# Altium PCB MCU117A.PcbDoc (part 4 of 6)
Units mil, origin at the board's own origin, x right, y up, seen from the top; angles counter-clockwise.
Board outline 2300 x 6749.64 mil, 6 copper layers (Top Signal, GND, Middle Signal, PWR, GND2, Bottom Signal), stack 61.64 mil thick; 424 components, 343 nets, 1563 pads, 921 vias.
Unrouted connection lines stored in the file: 4.
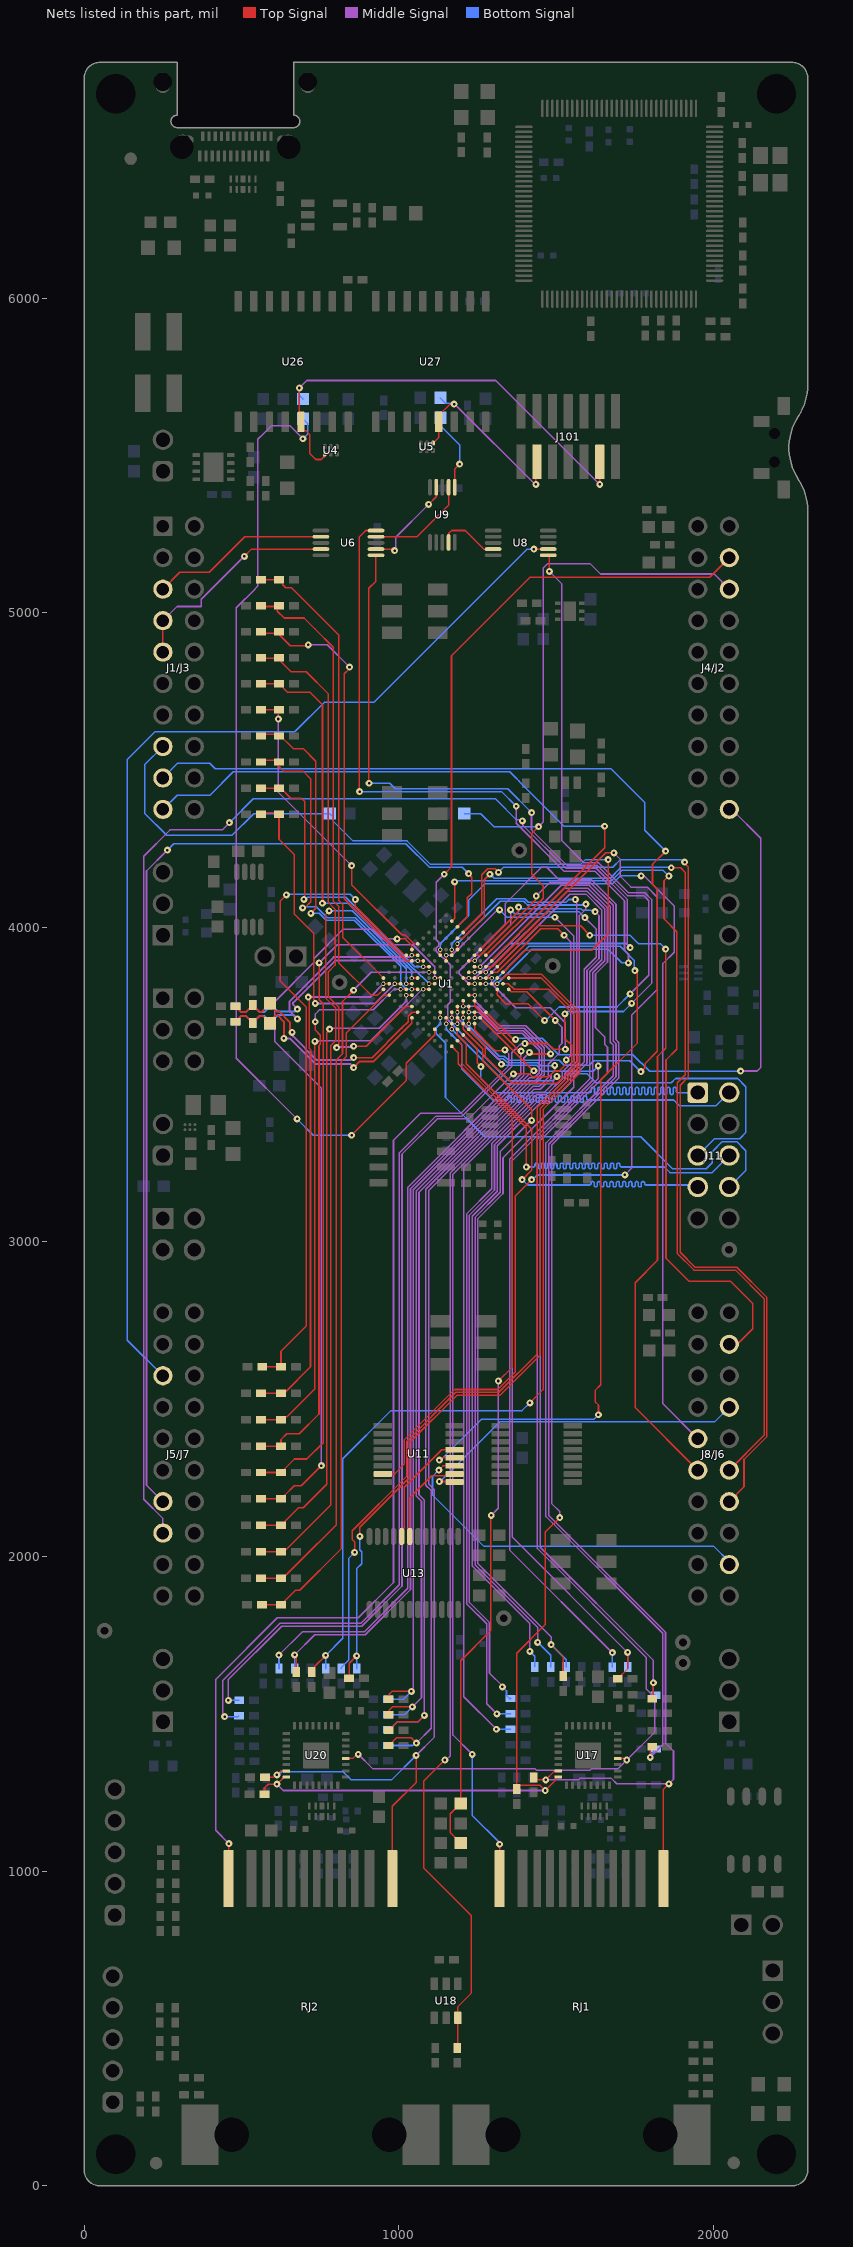
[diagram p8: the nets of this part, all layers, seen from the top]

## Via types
v1: diameter 22, hole 8, Top Signal to Bottom Signal, tented both sides, 821 vias
v2: diameter 14, hole 8, Top Signal to Bottom Signal, tented both sides, 82 vias
v3: diameter 19.68, hole 7.87, Top Signal to Bottom Signal, tented top, 14 vias
v4: diameter 15.75, hole 7.87, Top Signal to Bottom Signal, tented both sides, 2 vias
v5: diameter 19.68, hole 7.87, Top Signal to Bottom Signal, 2 vias

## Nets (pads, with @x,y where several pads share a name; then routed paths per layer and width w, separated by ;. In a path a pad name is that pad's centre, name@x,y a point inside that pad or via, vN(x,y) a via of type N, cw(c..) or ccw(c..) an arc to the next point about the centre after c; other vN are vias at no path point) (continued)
GPIO42: U1.C12 U6.6 | length 2639
  Top Signal w4: U1.C12@1312.81,3802.59 1312.81,3785.05 1340.29,3757.57 1409.23,3757.57
  Top Signal w5: v1(905.56,4457.76) 904.36,4458.97 904.36,5077.28 926.45,5099.38 926.45,5181.41 U6.6@927.34,5182.29 ; 1409.23,3757.57 v1(1462.86,3703.94)
  Middle Signal w5: v1(1421.5,4364.56) 1421.5,4309.46 1534.58,4196.38 1630.75,4196.38 1726.24,4100.89 1777.83,4100.89 1794.1,4084.62 1794.1,3847.43 v1(1735.08,3788.42)
  Bottom Signal w5: v1(905.56,4457.76) 970.51,4457.76 988.05,4440.23 1345.83,4440.23 v1(1421.5,4364.56) ; v1(1462.86,3703.94) 1466.46,3703.94 1509.2,3746.69 1693.35,3746.69 v1(1735.08,3788.42)
GPIO42_BP: J1/J3.4 J1/J3.5 U6.4 | length 709.9
  Top Signal w5: J1/J3.5@249.99,4874.64 J1/J3.4@249.99,4974.64 ; v1(509,5179.11) 531.86,5201.98 U6.4@752.14,5201.98
  Middle Signal w5: J1/J3.4@249.99,4974.64 294.99,5019.64 371.95,5019.64 371.95,5042.84 508.22,5179.11 v1(509,5179.11)
GPIO42_SCITX: U6.7 U9.9 | length 317.3
  Top Signal w5: U6.7@927.34,5201.98 981.13,5201.98 v1(986.18,5196.93) ; v1(1094.26,5344) 1118.5,5368.23 U9.9@1118.5,5398.49
  Middle Signal w5: v1(986.18,5196.93) 989.91,5200.67 989.91,5239.65 v1(1094.26,5344)
GPIO43: U1.C11 U6.10 | length 2589.7
  Top Signal w5: v1(875.05,4431.23) 874.62,4431.66 874.62,5241.35 894.31,5261.03 U6.10@927.34,5261.03 ; U1.C11@1294.71,3820.69 v2(1312.81,3820.69)
  Middle Signal w5: v1(1372.87,4384.62) 1372.87,4330.4 1524.89,4178.38 1623.29,4178.38 1717.06,4084.62 1717.06,3928.1 1729.67,3915.48 v1(1729.67,3887.06)
  Bottom Signal w4: v2(1312.81,3820.69) 1407.37,3915.25
  Bottom Signal w5: v1(875.05,4431.23) 1326.26,4431.23 v1(1372.87,4384.62) ; 1407.37,3915.25 1422.56,3930.44 1664.86,3930.44 1708.24,3887.06 v1(1729.67,3887.06)
GPIO43_BP: J1/J3.3 U6.2 | length 571.2
  Top Signal w5: J1/J3.3@249.99,5074.64 303.73,5128.38 397.49,5128.38 510.46,5241.35 U6.2@752.14,5241.35
GPIO43_SCIRX: U6.9 U9.7 | length 328.9
  Top Signal w5: U6.9@927.34,5241.35 1057.47,5241.35 1157.87,5341.74 U9.7@1157.87,5398.49
GPIO44: R146.2 R155.1 U1.F10 | length 2841.3
  Top Signal w5: v1(668.56,1687.49) 673.15,1682.89 R146.2@673.15,1632.93 ; U1.F10@1222.33,3784.5 v2(1240.43,3784.5) ; v1(1414.96,3602.28) 1419.56,3602.28 1424.45,3597.4 v1(1482.24,3597.4)
  Middle Signal w4: v2(1240.43,3784.5) 1240.43,3766.4 1319.69,3687.14 1402.56,3687.14 1479.25,3610.45 1479.25,3600.39 v1(1482.24,3597.4)
  Middle Signal w5: v1(668.56,1687.49) 732.72,1751.65 893.28,1751.65 1036.85,1895.21 1036.85,3169.28 1396.63,3529.06 1396.63,3583.95 v1(1414.96,3602.28)
  Bottom Signal w5: R155.1@668.56,1643.85 v1(668.56,1687.49)
GPIO45: R91.2 U1.F11 | length 2621.1
  Top Signal w4: U1.F11@1240.43,3766.4 1240.43,3748.77 1355.07,3634.12 1382.81,3606.38 v1(1388.33,3606.38)
  Middle Signal w5: v1(618.85,1686.88) 692.62,1760.65 889.55,1760.65 1027.85,1898.94 1027.85,3173.01 1387.63,3532.79 1387.63,3605.68 v1(1388.33,3606.38)
  Bottom Signal w5: R91.2@618.85,1643.85 v1(618.85,1686.88)
GPIO48_PHYCLK: R25.1 R27.1 U1.M13 | length 2706.8
  Top Signal w5: U1.M13@1168.05,3621.64 1188.99,3600.7 1188.99,3566.12 1360.87,3394.24 1360.87,2602.87 v1(1316,2558) ; R25.1@1196.24,1090.02 1163.53,1122.73 1163.53,1182.32 R27.1@1196.24,1215.02 1196.24,1669.26 1291.28,1764.3 1291.28,2128.65 v1(1293.53,2130.91)
  Middle Signal w5: v1(1293.53,2130.91) 1316,2153.37 v1(1316,2558)
GPIO49_FSITXD0: J11.6 U1.L13 | length 1534.2
  Top Signal w5: U1.L13@1186.14,3639.74 1199.14,3626.74 1199.14,3568.7 1405.03,3362.81 v1(1405.03,3238.18)
  Bottom Signal w5: v1(1405.03,3238.18) 1425.03,3238.18 1427.53,3238.18 ccw(c1427.53,3243.18) 1432.53,3243.18 1432.53,3245.6 cw(c1437.53,3245.6) 1442.53,3245.6 1442.53,3237.81 ccw(c1447.53,3237.81) 1452.53,3237.81 1452.53,3245.6 cw(c1457.53,3245.6) 1462.53,3245.6 1462.53,3237.81 ccw(c1467.53,3237.81) 1472.53,3237.81 1472.53,3245.6 cw(c1477.53,3245.6) 1482.53,3245.6 1482.53,3237.81 ccw(c1487.53,3237.81) 1492.53,3237.81 1492.53,3245.6 cw(c1497.53,3245.6) 1502.53,3245.6 1502.53,3237.81 ccw(c1507.53,3237.81) 1512.53,3237.81 1512.53,3245.6 cw(c1517.53,3245.6) 1522.53,3245.6 1522.53,3237.81 ccw(c1527.53,3237.81) 1532.53,3237.81 1532.53,3245.6 cw(c1537.53,3245.6) 1542.53,3245.6 1542.53,3237.81 ccw(c1547.53,3237.81) 1552.53,3237.81 1552.53,3245.6 cw(c1557.53,3245.6) 1562.53,3245.6 1562.53,3237.81 ccw(c1567.53,3237.81) 1572.53,3237.81 1572.53,3245.6 cw(c1577.53,3245.6) 1582.53,3245.6 1582.53,3237.81 ccw(c1587.53,3237.81) 1592.53,3237.81 1592.53,3245.6 cw(c1597.53,3245.6) 1602.53,3245.6 1602.53,3237.81 ccw(c1607.53,3237.81) 1612.53,3237.81 1612.53,3245.6 cw(c1617.53,3245.6) 1622.53,3245.6 1622.53,3237.81 ccw(c1627.53,3237.81) 1632.53,3237.81 1632.53,3245.6 cw(c1637.53,3245.6) 1642.53,3245.6 1642.53,3237.81 ccw(c1647.53,3237.81) 1652.53,3237.81 1652.53,3245.6 cw(c1657.53,3245.6) 1662.53,3245.6 1662.53,3237.81 ccw(c1667.53,3237.81) 1672.53,3237.81 1672.53,3245.6 cw(c1677.53,3245.6) 1682.53,3245.6 1682.53,3237.81 ccw(c1687.53,3237.81) 1692.53,3237.81 1692.53,3245.6 cw(c1697.53,3245.6) 1702.53,3245.6 1702.53,3243.18 ccw(c1707.53,3243.18) 1707.53,3238.18 1725.9,3238.18 1843.62,3238.18 1861.37,3220.43 1995.78,3220.43 J11.6@2049.99,3274.64
GPIO50_FSITXD1: J11.8 U1.K9 | length 1542
  Top Signal w5: v2(1131.86,3712.12) U1.K9@1131.86,3730.21
  Bottom Signal w4: v2(1131.86,3712.12) 1131.86,3694.09 1119.11,3681.34 1119.11,3661.81 1147.99,3632.93
  Bottom Signal w5: 1147.99,3632.93 1147.99,3589.5 1148.03,3589.46 1148.03,3584.07 1147.99,3584.03 1147.99,3459.13 1272.59,3334.53 1768.3,3334.53 1869.83,3233 1977,3233 1995.78,3251.78 1995.78,3286.82 2027.96,3319 2073.52,3319 2102.75,3289.77 2102.75,3227.4 J11.8@2049.99,3174.64
GPIO51_FSITXCLK: J11.2 U1.K10 | length 1528.9
  Top Signal w5: v2(1149.95,3694.02) U1.K10@1149.95,3712.12
  Bottom Signal w4: v2(1149.95,3694.02) 1149.95,3675.93 1199.14,3626.74
  Bottom Signal w5: 1199.14,3626.74 1199.14,3550.6 1298.68,3451.06 1330.61,3451.06 1341.5,3451.06 ccw(c1341.5,3456.06) 1346.5,3456.06 1346.5,3459.81 cw(c1351.5,3459.81) 1356.5,3459.81 1356.5,3448.37 ccw(c1361.5,3448.37) 1366.5,3448.37 1366.5,3459.81 cw(c1371.5,3459.81) 1376.5,3459.81 1376.5,3448.37 ccw(c1381.5,3448.37) 1386.5,3448.37 1386.5,3459.81 cw(c1391.5,3459.81) 1396.5,3459.81 1396.5,3448.37 ccw(c1401.5,3448.37) 1406.5,3448.37 1406.5,3459.81 cw(c1411.5,3459.81) 1416.5,3459.81 1416.5,3448.37 ccw(c1421.5,3448.37) 1426.5,3448.37 1426.5,3459.81 cw(c1431.5,3459.81) 1436.5,3459.81 1436.5,3448.37 ccw(c1441.5,3448.37) 1446.5,3448.37 1446.5,3459.81 cw(c1451.5,3459.81) 1456.5,3459.81 1456.5,3448.37 ccw(c1461.5,3448.37) 1466.5,3448.37 1466.5,3459.81 cw(c1471.5,3459.81) 1476.5,3459.81 1476.5,3448.37 ccw(c1481.5,3448.37) 1486.5,3448.37 1486.5,3459.81 cw(c1491.5,3459.81) 1496.5,3459.81 1496.5,3448.37 ccw(c1501.5,3448.37) 1506.5,3448.37 1506.5,3459.81 cw(c1511.5,3459.81) 1516.5,3459.81 1516.5,3448.37 ccw(c1521.5,3448.37) 1526.5,3448.37 1526.5,3459.81 cw(c1531.5,3459.81) 1536.5,3459.81 1536.5,3448.37 ccw(c1541.5,3448.37) 1546.5,3448.37 1546.5,3459.81 cw(c1551.5,3459.81) 1556.5,3459.81 1556.5,3448.37 ccw(c1561.5,3448.37) 1566.5,3448.37 1566.5,3459.81 cw(c1571.5,3459.81) 1576.5,3459.81 1576.5,3448.37 ccw(c1581.5,3448.37) 1586.5,3448.37 1586.5,3459.81 cw(c1591.5,3459.81) 1596.5,3459.81 1596.5,3456.06 ccw(c1601.5,3456.06) 1601.5,3451.06 1614,3451.06 1873.34,3451.06 1890.91,3433.49 2008.84,3433.49 J11.2@2049.99,3474.64
GPIO52_FSIRXD0: J11.5 U1.K11 | length 1394.5
  Top Signal w5: v2(1168.05,3675.93) U1.K11@1168.05,3694.02
  Bottom Signal w4: v2(1168.05,3675.93) 1340.78,3503.19
  Bottom Signal w5: 1340.78,3503.19 1503.34,3503.19 1534.84,3534.69 1597.75,3534.69 1626.64,3505.8 1865.77,3505.8 1879.32,3519.35 2076.65,3519.35 2102.75,3493.25 2102.75,3347.44 2083.31,3328 2003.35,3328 J11.5@1949.99,3274.64
GPIO53_FSIRXD1: J11.7 U1.K12 | length 1375.3
  Top Signal w4: U1.K12@1186.14,3675.93 1186.14,3657.83 1213.79,3630.18 1213.79,3566.77 1214.26,3566.3
  Top Signal w5: 1214.26,3566.3 1422.25,3358.32 1422.25,3228.51 v1(1391.77,3198.04)
  Bottom Signal w5: v1(1391.77,3198.04) 1408.97,3180.84 1603.28,3180.84 1605.78,3180.84 ccw(c1605.78,3185.84) 1610.78,3185.84 1610.78,3187.01 cw(c1615.78,3187.01) 1620.78,3187.01 1620.78,3179.89 ccw(c1625.78,3179.89) 1630.78,3179.89 1630.78,3187.01 cw(c1635.78,3187.01) 1640.78,3187.01 1640.78,3179.89 ccw(c1645.78,3179.89) 1650.78,3179.89 1650.78,3187.01 cw(c1655.78,3187.01) 1660.78,3187.01 1660.78,3179.89 ccw(c1665.78,3179.89) 1670.78,3179.89 1670.78,3187.01 cw(c1675.78,3187.01) 1680.78,3187.01 1680.78,3179.89 ccw(c1685.78,3179.89) 1690.78,3179.89 1690.78,3187.01 cw(c1695.78,3187.01) 1700.78,3187.01 1700.78,3179.89 ccw(c1705.78,3179.89) 1710.78,3179.89 1710.78,3187.01 cw(c1715.78,3187.01) 1720.78,3187.01 1720.78,3179.89 ccw(c1725.78,3179.89) 1730.78,3179.89 1730.78,3187.01 cw(c1735.78,3187.01) 1740.78,3187.01 1740.78,3179.89 ccw(c1745.78,3179.89) 1750.78,3179.89 1750.78,3187.01 cw(c1755.78,3187.01) 1760.78,3187.01 1760.78,3179.89 ccw(c1765.78,3179.89) 1770.78,3179.89 1770.78,3187.01 cw(c1775.78,3187.01) 1780.78,3187.01 1780.78,3185.84 ccw(c1785.78,3185.84) 1785.78,3180.84 1802.97,3180.84 1943.79,3180.84 J11.7@1949.99,3174.64
GPIO54_FSIRXCLK: J11.1 U1.K13 | length 1388.5
  Top Signal w4: U1.K13@1204.24,3657.83 1248.53,3613.54 1248.53,3569.56 1260.52,3557.57 v1(1260.52,3557.51)
  Bottom Signal w5: v1(1260.52,3557.51) 1260.52,3519.1 1304.98,3474.64 1597.26,3474.64 1606.72,3474.64 ccw(c1606.72,3479.64) 1611.72,3479.64 1611.72,3486.6 cw(c1616.72,3486.6) 1621.72,3486.6 1621.72,3473.34 ccw(c1626.72,3473.34) 1631.72,3473.34 1631.72,3486.6 cw(c1636.72,3486.6) 1641.72,3486.6 1641.72,3473.34 ccw(c1646.72,3473.34) 1651.72,3473.34 1651.72,3486.6 cw(c1656.72,3486.6) 1661.72,3486.6 1661.72,3473.34 ccw(c1666.72,3473.34) 1671.72,3473.34 1671.72,3486.6 cw(c1676.72,3486.6) 1681.72,3486.6 1681.72,3473.34 ccw(c1686.72,3473.34) 1691.72,3473.34 1691.72,3486.6 cw(c1696.72,3486.6) 1701.72,3486.6 1701.72,3473.34 ccw(c1706.72,3473.34) 1711.72,3473.34 1711.72,3486.6 cw(c1716.72,3486.6) 1721.72,3486.6 1721.72,3473.34 ccw(c1726.72,3473.34) 1731.72,3473.34 1731.72,3486.6 cw(c1736.72,3486.6) 1741.72,3486.6 1741.72,3473.34 ccw(c1746.72,3473.34) 1751.72,3473.34 1751.72,3486.6 cw(c1756.72,3486.6) 1761.72,3486.6 1761.72,3473.34 ccw(c1766.72,3473.34) 1771.72,3473.34 1771.72,3486.6 cw(c1776.72,3486.6) 1781.72,3486.6 1781.72,3473.34 ccw(c1786.72,3473.34) 1791.72,3473.34 1791.72,3486.6 cw(c1796.72,3486.6) 1801.72,3486.6 1801.72,3473.34 ccw(c1806.72,3473.34) 1811.72,3473.34 1811.72,3486.6 cw(c1816.72,3486.6) 1821.72,3486.6 1821.72,3473.34 ccw(c1826.72,3473.34) 1831.72,3473.34 1831.72,3486.6 cw(c1836.72,3486.6) 1841.72,3486.6 1841.72,3473.34 ccw(c1846.72,3473.34) 1851.72,3473.34 1851.72,3486.6 cw(c1856.72,3486.6) 1861.72,3486.6 1861.72,3473.34 ccw(c1866.72,3473.34) 1871.72,3473.34 1871.72,3486.6 cw(c1876.72,3486.6) 1881.72,3486.6 1881.72,3479.64 ccw(c1886.72,3479.64) 1886.72,3474.64 1899.22,3474.64 J11.1@1949.99,3474.64
GPIO55: U1.J13 U8.6 | length 2491.2
  Top Signal w4: U1.J13@1222.33,3675.93 1274.93,3623.33 1274.93,3589.01 1360.25,3503.69 1503.84,3503.69 1548.69,3548.54 1548.69,3625.09 1527.77,3646 v1(1527.77,3724.61)
  Top Signal w5: U8.6@1474.6,5182.29 1475.22,5182.29 1478.37,5179.15 v1(1478.37,5131)
  Middle Signal w5: v1(1478.37,5131) 1516.92,5092.45 1516.92,4276.36 1587.89,4205.38 1634.48,4205.38 1729.97,4109.89 1781.56,4109.89 1803.1,4088.35 1803.1,3821.63 v1(1739.52,3758.05)
  Bottom Signal w5: v1(1527.77,3724.61) 1535.58,3732.42 1713.89,3732.42 v1(1739.52,3758.05)
GPIO55_BP: J5/J7.43 U8.7 | length 3620
  Top Signal w5: v1(1429.06,5201.71) 1474.33,5201.71 U8.7@1474.6,5201.98
  Bottom Signal w5: J5/J7.43@249.99,2574.64 137,2687.63 137,4533.27 224.86,4621.14 668.97,4621.14 763.4,4715.56 921.19,4715.56 1407.33,5201.71 v1(1429.06,5201.71)
GPIO55_SCIRX: U8.4 U9.4 | length 198.1
  Top Signal w5: U9.4@1157.87,5223.29 1158.63,5224.06 1158.63,5252.15 1167.51,5261.03 1211.02,5261.03 1269.93,5202.13 1299.25,5202.13 U8.4@1299.4,5201.98
GPIO56: R58.2 U1.J12 | length 2307
  Top Signal w4: U1.J12@1204.24,3694.02 1204.24,3676.48 1266.43,3614.29
  Top Signal w5: 1266.43,3614.29 1266.43,3575.93 1422.06,3420.3 v1(1422.06,3386.33)
  Middle Signal w5: v1@1419.34,3384.88 1321.89,3287.43 1321.89,3157.62 1242.19,3077.92 1242.19,1973.73 1251.66,1964.26 1441,1774.92 v1(1441,1727.23)
  Bottom Signal w4: v1(1441,1727.23) 1482.44,1685.8 R58.2@1482.44,1648.7
GPIO57: J4/J2.19 U1.J11 | length 2269.3
  Top Signal w5: v1(1144.1,4168.54) 1167.12,4191.57 1167.12,4863.12 1416.65,5112.65 1988,5112.65 J4/J2.19@2049.99,5174.64 ; v2(1186.14,3694.02) U1.J11@1186.14,3712.12
  Middle Signal w4: v1(1144.1,4168.54) 1119.16,4143.6 1119.16,3960.19 1126.46,3952.89 1126.46,3942.1 1119.16,3934.79 1119.16,3924 1162.65,3880.51 1162.65,3761.14 1155.35,3753.84 1155.35,3706.86 1168.18,3694.02 v2(1186.14,3694.02)
GPIO58: RJ1.12 U1.J10 | length 3216.6
  Top Signal w5: v2(1168.05,3712.12) U1.J10@1168.05,3730.21 ; RJ1.12@1320.32,976.57 v1(1320.32,1085.68)
  Middle Signal w5: v1(1233.19,1371.59) 1171.79,1432.99 1171.79,3215.13 1432.85,3476.19 1463.61,3476.19 1490.61,3503.19 1490.61,3511.91 1501.81,3523.11 v1(1501.81,3525.99)
  Bottom Signal w4: v2(1168.05,3712.12) 1168.05,3694.09 1333.44,3528.7
  Bottom Signal w5: v1(1233.19,1371.59) 1233.19,1177.23 1320.32,1090.1 v1(1320.32,1085.68) ; 1333.44,3528.7 1349.94,3512.19 1488.02,3512.19 v1(1501.81,3525.99)
GPIO59: RJ2.12 U1.H13 | length 3415.2
  Top Signal w4: RJ2.12@458.6,976.57 458.6,1087.26 v1(459.35,1088) ; U1.H13@1240.43,3694.02 1240.43,3672.47 1295.83,3617.07 1305.61,3607.29 1333.59,3607.29 v1(1336.62,3610.32)
  Middle Signal w5: v1(459.35,1088) 417.53,1129.82 417.53,1609.51 613.66,1805.65 870.91,1805.65 982.85,1917.58 982.85,3323.45 1068.4,3409 1197.63,3409 1349.55,3560.92 1349.55,3597.4 v1(1336.62,3610.32)
GPIO61: R140.1 U1.H11 U18.3 | length 3775.4
  Top Signal w5: v1(1145.93,1353.47) 1079.02,1286.56 1079.02,1010.4 1229.38,860.05 1229.38,611.58 1187.62,569.82 U18.3@1187.62,533.72 1187.62,441.18 R140.1@1185.06,438.62 ; v2(1204.24,3712.12) U1.H11@1204.24,3730.21
  Middle Signal w5: v1(1145.93,1353.47) 1149.96,1353.47 1162.79,1366.3 1162.79,3218.86 1429.13,3485.19 1449.38,3485.19 1483.4,3519.21 1483.4,3531.9 1495.38,3543.88 v1(1495.38,3561.12) ; v1@1496.86,3559.64 v1@1497.24,3560.02
  Bottom Signal w4: v2(1204.24,3712.12) 1204.24,3693.44 1314.8,3582.88 1332.14,3582.88 1346.1,3568.92 1441.56,3568.92 1450.46,3560.02 v1@1497.24,3560.02
GPIO62: U1.H10 U17.12 U20.12 | length 4006.1
  Top Signal w5: U20.12@831.33,1358.36 854.44,1358.36 867.67,1371.59 v1(870.91,1371.59) ; v2(1186.14,3730.21) U1.H10@1186.14,3748.31 ; U17.12@1695.48,1358.36 1719.36,1358.36 v1(1724.25,1353.47)
  Middle Signal w4: v2(1186.14,3730.21) 1186.14,3712.05 1322.61,3575.59 1322.61,3568.25 v1(1326.05,3564.8)
  Middle Signal w5: v1(870.91,1371.59) 916.37,1326.13 1431.49,1326.13 1436.96,1320.66 1607.64,1320.66 1613.11,1326.13 1696.91,1326.13 v1(1724.25,1353.47) 1813.61,1442.83 1813.61,1552.25 1786.44,1579.43 1786.44,1679.44 1440.31,2025.57 1440.31,3325.78 1624.84,3510.31 1624.84,3510.51 1633.62,3519.29 v1(1633.62,3559.29)
  Bottom Signal w4: v1(1326.05,3564.8) 1329.49,3561.36 1336.95,3561.36 1337.39,3560.92 1438.25,3560.92 1455.98,3543.19 1617.52,3543.19 v1(1633.62,3559.29)
GPIO63: R158.1 R162.2 U1.G13 | length 2552.6
  Top Signal w4: U1.G13@1258.52,3712.12 1376.25,3594.39 1376.55,3594.39 v1@1428.59,3542.35
  Top Signal w5: R162.2@967.59,1546.11 969,1547.53 969,1562.72 977.83,1571.55 v1(1039.38,1571.55)
  Middle Signal w5: v1(1039.38,1571.55) 1039.38,1576.15 1045.85,1582.62 1045.85,3165.55 1414.38,3534.09 1415.12,3534.09 1425.18,3544.15 v1(1429.09,3544.15)
  Bottom Signal w5: R158.1@965.62,1546.11 1013.95,1546.11 v1(1039.38,1571.55)
GPIO64: R147.2 R150.1 U1.G12 | length 2724.3
  Top Signal w5: R147.2@967.59,1497.27 969,1498.68 969,1512.62 978.52,1522.14 v1(1042.56,1522.14) ; v2(1240.43,3712.12) U1.G12@1240.43,3730.21
  Middle Signal w4: v2(1240.43,3712.12) 1258.52,3712.12 1307.5,3663.14 1392.44,3663.14 1445.79,3609.8 1445.79,3537.23 1429.75,3521.19 1414.21,3521.19
  Middle Signal w5: v1(1042.56,1522.14) 1071.85,1551.43 1071.85,2175.74 1054.85,2192.73 1054.85,3161.83 1414.21,3521.19
  Bottom Signal w5: R150.1@965.62,1497.38 1017.8,1497.38 v1(1042.56,1522.14)
GPIO65: R145.1 R152.1 U1.G11 | length 2859.8
  Top Signal w5: R145.1@967.59,1448.42 969,1448.42 995.29,1474.7 1060.45,1474.7 v1(1080.85,1495.09) ; v2(1222.33,3730.21) U1.G11@1222.33,3748.31
  Middle Signal w4: v2(1222.33,3730.21) 1253.99,3730.21 1313.06,3671.14 1395.76,3671.14 1453.79,3613.11 1453.79,3533.91 1432.56,3512.69 1418.44,3512.69 1417.94,3512.19
  Middle Signal w5: v1(1080.85,1495.09) 1080.85,2179.47 1063.85,2196.46 1063.85,3158.1 1417.94,3512.19
  Bottom Signal w5: R152.1@965.62,1448.97 969.56,1448.97 995.29,1474.7 1060.45,1474.7 v1(1080.85,1495.09)
GPIO66: R133.1 R153.1 U1.G10 | length 2928.1
  Top Signal w5: R133.1@967.59,1399.57 992.09,1424.06 1039.01,1424.06 v1(1055.86,1407.22) ; v2(1204.24,3748.31) U1.G10@1204.24,3766.4
  Middle Signal w4: v2(1204.24,3748.31) 1247.21,3748.31 1316.38,3679.14 1399.07,3679.14 1461.79,3616.43 1461.79,3530.6 1434.88,3503.69 1422.17,3503.69 1421.67,3503.19
  Middle Signal w5: v1(1055.86,1407.22) 1102.87,1454.23 1102.87,2209.76 1085.67,2226.96 1085.67,3167.19 1421.67,3503.19
  Bottom Signal w5: R153.1@965.62,1399.57 1043.61,1399.57 1051.25,1407.22 v1(1055.86,1407.22)
GPIO68: R163.1 RJ2.1 U1.B13 U20.31 | length 3740.6
  Top Signal w4: U1.B13@1349,3802.59 1357,3794.59 1406.32,3794.59 v1(1496.98,3703.94)
  Top Signal w5: R163.1@574.12,1298.22 600.23,1298.22 607.88,1305.87 v1(612.48,1305.87) 625.6,1318.99 U20.31@642.35,1318.99 ; RJ2.1@979.08,976.57 979.08,1206.48 1054.85,1282.25 v1(1054.85,1368.2)
  Middle Signal w5: v1(1054.85,1368.2) 1111.87,1425.22 1111.87,2213.49 1094.67,2230.69 1094.67,3163.46 1425.4,3494.19 1445.66,3494.19 1474.4,3522.93 1474.4,3564.46 1509.01,3599.07 1509.01,3622.16 1518.48,3631.62 1518.48,3682.44 v1(1496.98,3703.94)
  Bottom Signal w5: v1(612.48,1305.87) 617.08,1305.87 627.54,1316.33 822.15,1316.33 847.35,1291.13 977.78,1291.13 v1(1054.85,1368.2)
GPIO69: R148.1 U1.B12 | length 2738.2
  Top Signal w4: U1.B12@1330.9,3820.69 1347.89,3820.69 1365.98,3802.59 1463.42,3802.59
  Top Signal w5: v1(859.39,2013.6) 859.39,2046.35 851.78,2053.96 851.78,2082.11 1025.49,2255.82 1025.49,2366.77 1180.72,2522 1317.7,2522 1440.31,2644.61 1440.31,3428.14 1507.36,3495.19 1557.19,3545.01 1557.19,3721.39 1475.99,3802.59 1463.42,3802.59
  Bottom Signal w5: R148.1@816.71,1643.85 816.71,1647.79 841.08,1672.16 841.08,1995.29 v1(859.39,2013.6)
GPIO70: R149.1 R161.2 U1.A12 | length 2802.5
  Top Signal w5: R161.2@841.86,1612.97 841.86,1660.99 v1(865.45,1684.59) ; v1(875.73,2063.9) 875.73,2093.34 1034.49,2252.09 1034.49,2363.04 1184.45,2513 1321.42,2513 1449.31,2640.88 1449.31,3424.41 1511.09,3486.19 1566.19,3541.29 1566.19,3725.12 1452.52,3838.79 1388.13,3838.79 U1.A12@1349,3838.79
  Bottom Signal w5: R149.1@865.45,1643.85 v1(865.45,1684.59) 865.45,1961.01 881.93,1977.49 881.93,2015.3 875.73,2021.49 v1(875.73,2063.9)
GPIO71: R130.1 R154.1 U1.B11 | length 3052.9
  Top Signal w4: U1.B11@1312.81,3838.79 1332.16,3838.79 1344.07,3850.69 1440.75,3850.69
  Top Signal w5: R130.1@723.22,1632.93 732.53,1642.24 732.53,1651.12 v1(767.33,1685.93) ; v1(1416,2488.43) 1458.31,2530.74 1458.31,3420.68 1514.82,3477.19 1575.19,3537.56 1575.19,3728.85 1453.35,3850.69 1440.75,3850.69
  Bottom Signal w5: R154.1@767.33,1643.85 v1(767.33,1685.93) 821.49,1740.09 821.49,2310.82 974.68,2464 1391.57,2464 v1(1416,2488.43)
GPIO72: J1/J3.8 R31.1 U1.A11 | length 2468.7
  Top Signal w4: U1.A11@1330.9,3856.88 1401.36,3927.34 1613.48,3927.34 1654.03,3967.89
  Top Signal w5: 1654.03,3967.89 1664.86,3978.71 v1(1664.86,4215.33)
  Bottom Signal w5: J1/J3.8@249.99,4574.64 191.82,4516.47 191.82,4362.39 262.01,4292.2 469.65,4292.2 538.72,4361.28 R31.1@779.91,4361.28 790.82,4350.37 790.82,4338 854.24,4274.59 1025.74,4274.59 1100.6,4199.73 1577.34,4199.73 1592.94,4215.33 v1(1664.86,4215.33)
GPIO73: R110.2 U1.C10 | length 3335.7
  Top Signal w5: U1.C10@1276.62,3838.79 v2(1294.71,3838.79) ; v1(1400.34,3630.65) 1473.6,3630.65 1491.94,3612.3 v1(1528.87,3612.3)
  Middle Signal w4: v2(1294.71,3838.79) 1294.71,3820.82 1370.93,3744.61 1481.73,3744.61 1529.05,3697.29 1529.05,3612.48 v1(1528.87,3612.3)
  Middle Signal w5: v1(446.01,1491.64) 446.01,1496.24 439.81,1502.45 439.81,1606.34 621.12,1787.65 878.37,1787.65 1000.85,1910.13 1000.85,3283.03 1117.82,3400 1201.36,3400 1358.55,3557.19 1358.55,3600.92 1385.02,3627.4 1397.09,3627.4 v1(1400.34,3630.65)
  Bottom Signal w4: v1(446.01,1491.64) 488.95,1491.64 R110.2@491.68,1494.37
GPIO74: R144.2 U1.B10 | length 3517.5
  Top Signal w4: U1.B10@1294.71,3856.88 1312.26,3856.88 1450.49,3995.11 1504.85,3995.11 v1(1525.32,3974.64)
  Top Signal w5: v1(1364.11,3534.21) 1414.7,3534.21 1423.76,3525.15 1476.65,3525.15 1494.69,3543.19 1509.78,3543.19 1530.4,3563.81 1530.4,3576.81 v1(1531.99,3578.39)
  Middle Signal w5: v1(457.8,1542.86) 457.8,1609.19 627.26,1778.65 882.1,1778.65 1009.85,1906.4 1009.85,3279.3 1121.55,3391 1220.9,3391 v1(1364.11,3534.21) ; v1(1525.32,3974.64) 1546.41,3953.55 1546.41,3592.82 v1(1531.99,3578.39)
  Bottom Signal w4: v1(457.8,1542.86) R144.2@492.5,1542.86
GPIO75: J8/J6.75 U1.A10 | length 2398.1
  Top Signal w4: U1.A10@1312.81,3874.98 1441.95,4004.11 1577.16,4004.11 v1(1606.63,3974.64)
  Top Signal w5: v1@1848.03,3930.89 1848.03,3615.75 1821.8,3589.51 1821.8,2941.58 1750.82,2870.59 1750.82,2473.82 J8/J6.75@1949.99,2274.64
  Bottom Signal w5: v1(1606.63,3974.64) 1734.29,3974.64 1761.45,3947.49 1831.43,3947.49 v1@1848.03,3930.89
  other v1: 1847.81,3930.79
GPIO76: R32.2 R141.2 U1.E9 U17.32 U20.32 | length 4914.8
  Top Signal w5: R141.2@572.83,1245.25 572.83,1264.91 584.44,1276.52 612.68,1276.52 635.46,1299.3 U20.32@642.35,1299.3 ; U1.E9@1222.33,3820.69 v2(1240.43,3820.69) ; U17.32@1506.5,1299.3 1501.5,1299.3 1499.08,1296.88 1499.08,1290.54 v1(1465.03,1256.5) 1448.26,1273.27 1386.54,1273.27 R32.2@1374.33,1261.06 1374.33,1693.04 1465.24,1783.95 1465.24,2077.74 v1(1511.11,2123.62)
  Middle Signal w4: v2(1240.43,3820.69) 1221.78,3820.69 1217.5,3824.97 1217.5,3825.65 1191.54,3851.62 1191.54,3862.28 1338.55,4009.29 1338.55,4075.76
  Middle Signal w5: v1(612.48,1276.52) 632.49,1256.5 v1(1465.03,1256.5) ; 1338.55,4075.76 1453.52,4190.73 1469.67,4190.73 1509.01,4151.38 1612.11,4151.38 1690.06,4073.44 1690.06,3642.32 1699.06,3633.32 1699.06,3520.89 1485.31,3307.14 1485.31,2168.94 1511.11,2143.14 v1(1511.11,2123.62)
GPIO77: R114.1 U1.D9 | length 3199.3
  Top Signal w5: U1.D9@1240.43,3838.79 v2(1258.52,3838.79)
  Middle Signal w4: v2(1258.52,3838.79) 1276.48,3838.79 1543.29,4105.6
  Middle Signal w5: 1543.29,4105.6 1594.26,4105.6 1645.03,4054.82 1645.03,3897.21 1606.84,3859.01 1606.84,3517.77 1351.87,3262.8 1351.87,2021.03 v1(1678.42,1694.49)
  Bottom Signal w4: R114.1@1678.42,1648.36 v1(1678.42,1694.49)
GPIO78: R115.1 R127.2 U1.C9 | length 3305.6
  Top Signal w5: U1.C9@1258.52,3856.88 v2(1276.62,3856.88) ; R127.2@1695.5,1611.56 1726.85,1642.91 v1(1726.85,1695.24)
  Middle Signal w4: v2(1276.62,3856.88) 1534.33,4114.6 1539.57,4114.6
  Middle Signal w5: 1539.57,4114.6 1597.99,4114.6 1654.03,4058.55 1654.03,3893.48 1615.84,3855.29 1615.84,3514.04 1360.87,3259.07 1360.87,2061.23 v1(1726.85,1695.24)
  Bottom Signal w4: v2(1276.62,3856.88) v2@1276.62,3857.43 ; R115.1@1726.85,1648.71 v1(1726.85,1695.24)
GPIO79: U1.B9 U11.15 | length 3245.4
  Top Signal w4: U1.B9@1276.62,3874.98 1295.97,3874.98 1657.25,4236.25 v1(1683.26,4236.25)
  Top Signal w5: U11.15@949.11,2262.51 985.96,2262.51 1016.49,2293.04 1016.49,2370.49 1176.99,2531 1313.97,2531 1369.87,2586.9 1369.87,3146.18 v1(1421.73,3198.04)
  Middle Signal w5: v1(1683.26,4236.25) 1703.97,4215.55 1703.97,4161.35 1737.43,4127.89 1789.01,4127.89 1821.1,4095.81 1821.1,3802.08 1739.52,3720.5 1739.52,3234.08 v1(1718.28,3212.83)
  Bottom Signal w5: v1(1421.73,3198.04) 1424.82,3198.04 1439.61,3212.83 v1(1718.28,3212.83)
GPIO79_BP: J8/J6.57 U11.1 | length 1068.3
  Top Signal w5: v1(1128.7,2238.6) 1175.77,2238.6 U11.1@1177.46,2236.92
  Bottom Signal w5: v1@1129.5,2237.29 1320.21,2428 2003.35,2428 J8/J6.57@2049.99,2474.64
GPIO79_Q2B: U11.2 U13.7 | length 297.5
  Top Signal w5: U13.7@1034.49,2063.9 1034.49,2187.27 1104.29,2257.08 1172.02,2257.08 U11.2@1177.46,2262.51
GPIO80: R126.1 R128.2 U1.E8 | length 3432.2
  Top Signal w5: U1.E8@1204.24,3838.79 v2(1222.33,3838.79) ; R128.2@1805.13,1548 1809,1551.87 v1(1809,1599)
  Middle Signal w4: v2(1222.33,3838.79) 1240.43,3838.79 1526.03,4124.38
  Middle Signal w5: 1526.03,4124.38 1600.93,4124.38 1663.03,4062.28 1663.03,3889.75 1624.84,3851.56 1624.84,3680.42 1654.06,3651.2 1654.06,3627.41 1663.03,3618.43 1663.03,3535.78 1449.31,3322.05 1449.31,2029.29 1809,1669.6 v1(1809,1599)
  Bottom Signal w5: v1(1809,1599) 1809,1562.8 1812.02,1559.78 R126.1@1815.94,1559.78
GPIO82: J5/J7.48 U1.D8 | length 4641.8
  Top Signal w5: U1.D8@1222.33,3856.88 v2(1240.43,3856.88)
  Middle Signal w5: J5/J7.48@249.99,2074.64 249.99,2120.89 188.76,2182.12 188.76,4225.76 272.4,4309.4 438.26,4309.4 v1(461.49,4332.63) ; v1(1392.52,4338) 1394.46,4336.07 1394.46,4323.78 1530.85,4187.38 1627.02,4187.38 1726.41,4087.99 1726.41,3946.97 1735.08,3938.3 v1(1735.08,3935.55)
  Bottom Signal w4: v2(1240.43,3856.88) 1258.52,3856.88 1340.66,3939.02
  Bottom Signal w5: v1(461.49,4332.63) 537.35,4408.49 1306.8,4408.49 1374.04,4341.26 1389.27,4341.26 v1(1392.52,4338) ; 1340.66,3939.02 1350.09,3948.44 1722.19,3948.44 v1(1735.08,3935.55)
GPIO83: R89.1 R118.1 U1.C8 | length 3606.4
  Top Signal w5: U1.C8@1240.43,3874.98 v2(1258.52,3874.98) ; v1(1798.72,1361.93) 1798.72,1388.59 R89.1@1805.13,1395
  Middle Signal w4: v2@1258.52,3875.53 1516.38,4133.38
  Middle Signal w5: v2(1258.52,3874.98) v2@1258.52,3875.53 ; 1516.38,4133.38 1604.65,4133.38 1608.99,4129.05 1672.06,4065.98 1672.06,3634.86 1681.03,3625.89 1681.03,3625.82 1681.06,3553.8 1681.03,3528.32 1467.31,3314.6 1467.31,2127.09 1838.37,1756.03 1838.37,1401.58 v1(1798.72,1361.93)
  Bottom Signal w5: v1(1798.72,1361.93) 1798.72,1369.61 R118.1@1817.62,1388.5 ; R118.1@1817.62,1380.83 R118.1@1817.62,1383.79
GPIO84: J4/J2.18 R33.2 U1.A8 | length 2222.5
  Top Signal w4: U1.A8@1276.62,3911.17 1458.31,4092.86
  Top Signal w5: v1(1443.9,4319.84) 1422.25,4298.18 1422.25,4168.33 1458.31,4132.27 1458.31,4092.86
  Middle Signal w5: v1(1443.9,4319.84) 1458.2,4334.14 1458.2,5140.8 1473.43,5156.03 1607.62,5156.03 1640.86,5122.79 2001.84,5122.79 J4/J2.18@2049.99,5074.64
  Bottom Signal w5: R33.2@1207.62,4361.28 1260.49,4361.28 1301.93,4319.84 v1(1443.9,4319.84) v1@1445.71,4321.64
GPIO85: R112.2 R120.1 U1.A7 | length 3231.8
  Top Signal w4: U1.A7@1258.52,3929.26 1380.77,4051.51 v1(1380.77,4063.87)
  Top Signal w5: v1(1483.53,1720.34) 1522.97,1680.9 R112.2@1522.97,1620.38
  Middle Signal w5: v1(1483.53,1720.34) 1483.53,1745.12 1260.66,1967.99 1251.19,1977.46 1251.19,3074.19 1330.89,3153.89 1330.89,3267.27 1555.41,3491.79 1555.41,3525.49 1597.84,3567.92 1597.84,3862.74 1636.03,3900.93 1636.03,4037.18 v1(1623.34,4049.87)
  Bottom Signal w4: v1(1483.53,1720.34) 1531.6,1672.27 R120.1@1531.6,1648.77
  Bottom Signal w5: v1(1380.77,4063.87) 1384.3,4060.34 1385.77,4058.87 1545.43,4058.87 1579.13,4058.87 1584.27,4053.74 1611.91,4053.74 1612.52,4053.13 1620.09,4053.13 v1(1623.34,4049.87)
GPIO86: R129.2 RJ1.1 U1.B7 U17.31 | length 4428.3
  Top Signal w4: U1.B7@1240.43,3911.17 1257.97,3911.17 1433.35,4086.55 1433.35,4096.3 v1(1436.5,4099.44)
  Top Signal w5: R129.2@1428.56,1298.27 1436.29,1290.54 v1(1466.7,1290.54) 1492.73,1316.58 1504.09,1316.58 U17.31@1506.5,1318.99 ; RJ1.1@1840.79,976.57 1840.79,1260.4 v1(1857.99,1277.6)
  Middle Signal w5: v1(1436.5,4099.44) 1479.44,4142.38 1608.38,4142.38 1681.06,4069.71 1681.06,3638.59 1690.06,3629.59 1690.06,3550.07 ; v1(1466.7,1290.54) 1571.08,1290.54 1575.55,1295.01 1675.33,1295.01 1692.75,1277.6 v1(1857.99,1277.6) 1872.72,1292.32 1872.72,1382.24 1847.37,1407.59 1847.37,1759.76 1476.31,2130.82 1476.31,3310.87 1690.03,3524.59 1690.03,3550.05
GPIO87: R87.2 U1.C7 | length 3135.7
  Top Signal w5: U1.C7@1222.33,3893.07 v2(1240.43,3893.07)
  Middle Signal w4: v2(1240.43,3893.07) 1355.35,4008 v1(1355.35,4055.5)
  Middle Signal w5: v1(1416,1698.56) 1416,1787.19 1233.19,1970 1233.19,3081.65 1312.89,3161.34 1312.89,3305.31 1447.76,3440.19 1478.52,3440.19 1546.01,3507.68 1546.01,3528.83 1588.84,3571.65 1588.84,3866.47 1627.03,3904.66 1627.03,3994.54 v1(1591.01,4030.56)
  Bottom Signal w4: v2(1240.43,3893.07) v2@1240.43,3893.62 ; v1(1416,1698.56) 1432.06,1682.51 R87.2@1432.06,1649.47
  Bottom Signal w5: v1@1358.35,4053.47 1368.44,4043.39 1469.07,4043.39 1475.56,4049.87 1571.7,4049.87 v1(1591.01,4030.56)
GPIO88: R86.2 U1.C5 | length 3240.5
  Top Signal w5: U1.C5@1186.14,3929.26 v2(1186.14,3947.36)
  Middle Signal w5: v1(1328.96,1585.78) 1328.96,1588.38 1288,1629.34 1288,1790.13 1224.19,1853.94 1224.19,3085.37 1303.89,3165.07 1303.89,3309.04 1444.04,3449.19 1474.8,3449.19 1537.01,3511.41 1537.01,3532.55 1573.81,3569.35 1573.81,3868.38 1573.81,4037.69 1594.26,4058.14 v1(1594.26,4073.44)
  Bottom Signal w4: v2(1186.14,3947.36) 1321.5,4082.72 1396.82,4082.72
  Bottom Signal w5: v1(1328.96,1585.78) 1342.04,1572.7 1342.04,1558.22 1351.35,1548.91 R86.2@1355.1,1548.91 ; 1396.82,4082.72 1408.61,4070.93 1591.75,4070.93 v1(1594.26,4073.44)
GPIO89: R84.2 U1.D5 | length 3333
  Top Signal w5: U1.D5@1168.05,3911.17 v2(1168.05,3929.26)
  Middle Signal w5: v1(1311.13,1500.15) 1279,1532.28 1279,1786.4 1215.19,1850.21 1215.19,3089.1 1294.89,3168.8 1294.89,3312.77 1440.31,3458.19 1471.07,3458.19 1528.01,3515.14 1528.01,3536.28 1564.81,3573.07 1564.81,3864.65 1564.81,4076.92 1564.32,4077.41 1564.32,4085.1 v1(1561.06,4088.35)
  Bottom Signal w4: v2(1168.05,3929.26) 1168.05,3947.29 1311.61,4090.85 1355.79,4090.85 1356.16,4091.22 1400.34,4091.22 1411.36,4080.2 1412.82,4080.2
  Bottom Signal w5: v1(1311.13,1500.15) R84.2@1355.1,1500.15 ; 1412.82,4080.2 1531.79,4080.2 1539.99,4088.4 v1(1561.06,4088.35) v1(1561.06,4088.35)
GPIO90: R83.2 U1.E5 | length 3287.7
  Top Signal w5: U1.E5@1149.95,3893.07 v2(1149.95,3911.17)
  Middle Signal w4: v2(1149.95,3911.17) 1168.18,3911.17 1198.98,3941.96 1199.42,3941.96 1201.77,3944.3
  Middle Signal w5: 1201.77,3944.3 1312.77,4055.31 v1(1320.26,4055.31) ; v1(1309.92,1451.08) 1206.19,1554.81 1206.19,3236.8 1436.58,3467.19 1467.34,3467.19 1519.01,3518.86 1519.01,3540.01 1555.41,3576.4 1555.41,3972.34 v1(1495.82,4031.92)
  Bottom Signal w5: v1(1309.92,1451.08) R83.2@1355.1,1451.08 ; v1(1320.26,4055.31) 1343.44,4032.13 v1@1489.25,4032.13 ; v1@1320.53,4062.15 v1@1323.82,4058.86
GPIO91: J8/J6.55 U1.B4 | length 3050.7
  Top Signal w4: U1.B4@1186.14,3965.45 1203.69,3965.45 1271.98,4033.75 1271.98,4151.07 v1(1289.46,4168.54)
  Top Signal w5: v1(1865.66,4189.13) 1895.55,4189.13 1910.17,4174.51 1910.17,3530.96 1884.8,3505.59 1884.8,2963.29 1937.52,2910.57 2069.72,2910.57 2160.71,2819.58 2160.71,2385.36 J8/J6.55@2049.99,2274.64
  Bottom Signal w5: v1(1289.46,4168.54) 1291.06,4168.54 1303.34,4156.26 1671.44,4156.26 1705.67,4190.49 1864.3,4190.49 v1(1865.66,4189.13)
GPIO92: J8/J6.54 U1.A4 | length 3174.2
  Top Signal w4: U1.A4@1204.24,3983.55 1263.98,4043.29 1263.98,4167.39 1282.34,4185.74 1305.43,4185.74 v1(1316.53,4174.64)
  Top Signal w5: v1(1908.11,4207.39) 1908.11,4203.35 1919.17,4192.29 1919.17,3523.29 1893.8,3497.92 1893.8,2967.02 1941.25,2919.57 2073.44,2919.57 2169.71,2823.31 2169.71,2381.63 2096.88,2308.8 2096.88,2221.53 J8/J6.54@2049.99,2174.64
  Bottom Signal w5: v1(1316.53,4174.64) 1332.62,4190.73 1461.6,4190.73 1679.39,4190.73 1704,4215.33 1896.68,4215.33 1904.63,4207.39 v1(1908.11,4207.39)
GPIO93: J5/J7.47 U1.A3 | length 3316.6
  Top Signal w4: U1.A3@1186.14,4001.64 1217.22,4032.72 1217.22,4093.3 1231.03,4107.11 1231.03,4159.24 1221.78,4168.49 v1(1221.78,4170.58)
  Middle Signal w5: J5/J7.47@249.99,2174.64 197.76,2226.88 197.76,4178.95 264.01,4245.2 v1(264.25,4245.2)
  Bottom Signal w5: v1(264.25,4245.2) 284.64,4265.59 1022.02,4265.59 1096.87,4190.73 1201.64,4190.73 v1(1221.78,4170.58)
GPIO94: J8/J6.59 U1.A2 | length 2595.6
  Top Signal w4: U1.A2@1168.05,4019.74 1176.76,4028.45 v1(1176.76,4144.45)
  Top Signal w5: v1(1857.8,4163.04) 1842.58,4147.82 1842.58,4026.84 1883.17,3986.25 1883.17,3612.7 1848.8,3578.33 1848.8,2948.38 1895.61,2901.57 1901.17,2896.01 1922.61,2874.57 2054.8,2874.57 2124.71,2804.67 2124.71,2724.04 2075.31,2674.64 J8/J6.59@2049.99,2674.64
  Bottom Signal w5: v1(1176.76,4144.45) 1179.58,4147.26 1675.17,4147.26 1709.4,4181.49 1839.35,4181.49 v1(1857.8,4163.04)
GPIO99: J8/J6.76 U1.E4 | length 2691.1
  Top Signal w5: U1.E4@1131.86,3911.17 v2(1131.86,3929.26)
  Middle Signal w5: v1(1769.97,4163.51) 1778.85,4163.51 1875,4067.36 1875,3920.99 1839.1,3885.09 1839.1,2485.54 J8/J6.76@1949.99,2374.64
  Bottom Signal w4: v2(1131.86,3929.26) 1131.86,3947.49 1215.72,4031.36
  Bottom Signal w5: 1215.72,4031.36 1222.33,4037.97 1222.33,4087.09 1273.29,4138.05 1665.95,4138.05 1666.17,4138.26 1678.9,4138.26 1704.15,4163.51 v1(1769.97,4163.51)
GPIO103: U1.D10 U11.4 | length 2678.5
  Top Signal w5: v1(1128.75,2306.75) 1131.44,2306.75 1138.38,2313.69 U11.4@1177.46,2313.69 ; U1.D10@1258.52,3820.69 v2(1276.62,3820.69) ; v1(1634.28,2450.67) 1634.28,2481.45 1623.58,2492.15 1623.58,2528.04 1641.48,2545.94 1641.48,3515.39 1758.1,3632.01 1758.1,3854.26 v1(1749.82,3862.54)
  Bottom Signal w4: v2(1276.62,3820.69) 1294.71,3820.69 1397.56,3923.54
  Bottom Signal w5: v1@1132.57,2306.58 1262.99,2437 1620.61,2437 v1(1634.28,2450.67) ; 1397.56,3923.54 1413.47,3939.44 1703.22,3939.44 1748.6,3894.07 1748.6,3863.76 v1(1749.82,3862.54)
GPIO103_BP: J8/J6.52 U11.3 | length 1183.3
  Top Signal w5: v1(1127.02,2275) 1140.11,2288.1 U11.3@1177.46,2288.1
  Bottom Signal w5: v1(1127.02,2275) 1106.86,2254.84 1106.86,2195.73 1270.45,2032.14 2001.2,2032.14 2049.99,1983.34 J8/J6.52@2049.99,1974.64
GPIO103_Q2I: U11.5 U13.8 | length 369.4
  Top Signal w5: U13.8@1008.9,2063.9 1008.9,2083.63 1017.15,2091.89 1017.15,2220.35 1136.08,2339.28 U11.5@1177.46,2339.28
GPIO104: J1/J3.10 U1.A9 | length 2102.2
  Top Signal w4: U1.A9@1294.71,3893.07 1654.03,4252.39 v1(1654.03,4321.09)
  Bottom Signal w5: J1/J3.10@249.99,4374.64 295.35,4420 399.51,4420 473.55,4494.04 1352.06,4494.04 1371.13,4474.96 1371.56,4474.96 1381.63,4464.89 1381.63,4464.46 1525.01,4321.09 v1(1654.03,4321.09)
GPIO105: J1/J3.9 U1.H12 | length 3173.9
  Top Signal w5: v2(1222.33,3694.02) U1.H12@1222.33,3712.12 ; v1(1768.82,3541.29) 1782.55,3555.02 1782.55,3567.35 1821.1,3605.9 1821.1,4121.26 1805.97,4136.39 1805.97,4200.19 v1(1847.81,4242.04)
  Bottom Signal w4: v2(1222.33,3694.02) 1224.13,3692.22 1224.13,3685.44 1298.93,3610.64 1318.7,3590.88 1335.45,3590.88 1348.51,3577.82 1508.94,3577.82 1525.07,3561.69 1605.39,3561.69 1619.69,3575.99 1734.11,3575.99 v1(1768.82,3541.29)
  Bottom Signal w5: J1/J3.9@249.99,4474.64 296.35,4521 399.08,4521 416.02,4504.05 1673.9,4504.05 1781.49,4396.46 1781.49,4308.36 v1(1847.81,4242.04)
GPIO133: J4/J2.11 U1.F13 | length 1825.7
  Top Signal w4: U1.F13@1276.62,3730.21 1362.84,3644 v1(1370.8,3644)
  Middle Signal w5: J4/J2.11@2049.99,4374.64 2058.36,4374.64 2150.28,4282.72 2150.28,3554.28 2139.19,3543.19 v1(2086.05,3543.19)
  Bottom Signal w4: v1(1370.8,3644) 1374.15,3647.35 1456.19,3647.35 1507.95,3595.59 1743.84,3595.59 1796.68,3542.75 2085.62,3542.75 v1(2086.05,3543.19)
MCU_A0/DACA_OUT: C39.1 R18.2 U1.L3 | length 1011.2
  Top Signal w5: R18.2@562.95,4364.56 C39.1@627.65,4364.56 ; C39.1@618.95,4359.81 618.95,4279.78 667.66,4231.07 667.66,4042.12 729.34,3980.45 729.34,3769.48 730.81,3768.01 730.81,3761.31 v1(734.06,3758.05) ; v2(987.09,3820.69) U1.L3@1005.19,3820.69
  Middle Signal w6: v1(734.06,3758.05) 924.46,3758.05 v2(987.09,3820.69)
MCU_A4: C26.1 R38.2 U1.H2 | length 1368.8
  Top Signal w4: 826.28,4090.63 1023.84,3893.07 U1.H2@1041.38,3893.07
  Top Signal w5: R38.2@561.21,4934.64 614.99,4934.64 654.68,4894.96 709.3,4894.96 v1(711.95,4897.61) ; 826.28,4090.63 826.28,4805.95 843,4822.67 v1(843,4827)
  Middle Signal w5: v1(711.95,4897.61) 772.39,4897.61 v1(843,4827)
MCU_A5: C40.1 R39.2 U1.H1 | length 2109.8
  Top Signal w5: R39.2@565.62,2603.44 C40.1@625.3,2603.44 625.3,2652.85 706.13,2733.68 706.13,3745.9 622.76,3829.27 622.76,4083.36 v1(642.58,4103.18) ; v1@861.67,4088.33 861.67,4067.26 1016.46,3912.47 1021.98,3912.47 U1.H1@1023.28,3911.17
  Bottom Signal w4: v1(642.58,4103.18) 644.49,4105.1 844.91,4105.1 v1(861.65,4088.35)
MCU_A7: C27.1 R40.2 U1.K5 | length 1172.1
  Top Signal w5: R40.2@561.21,4613.13 618.93,4613.13 664.9,4567.16 696.44,4567.16 735.98,4527.62 735.98,4060.59 719.99,4044.61 v1(719.99,4044.05) ; v2(1041.38,3802.59) U1.K5@1059.47,3802.59
  Bottom Signal w4: v1(719.99,4044.05) 746.54,4044.05 768.33,4022.26 858.61,4022.26 1005.19,3875.68 1005.19,3820.69 1023.28,3802.59 v2(1041.38,3802.59)
MCU_A8: C41.1 R41.2 U1.J6 | length 1747.7
  Top Signal w5: R41.2@561.21,2435.35 C41.1@625.3,2435.35 634.11,2444.16 644.04,2444.16 649.79,2449.91 649.79,2450.06 653.89,2454.16 654.04,2454.16 732.99,2533.11 v1(732.99,3637.14) ; v2(1077.57,3802.59) U1.J6@1095.67,3802.59
  Middle Signal w5: v1(732.99,3637.14) 735.53,3639.68 910.33,3639.68 921.86,3651.2 983.39,3712.73 983.56,3712.73 987.66,3716.83 987.66,3716.91 988.08,3717.35 989.9,3719.24 1073.25,3802.59 v2(1077.57,3802.59)
MCU_A10: C29.1 R42.2 U1.L5 | length 2030.4
  Top Signal w5: R42.2@561.21,2099.15 C29.1@625.3,2099.15 681.15,2155 696,2155 770.83,2229.83 770.83,3664.96 779.68,3673.81 v1(779.68,3676.39) ; v2(1023.28,3784.5) U1.L5@1041.38,3784.5
  Middle Signal w5: v1@779.68,3679.43 937.36,3679.43 1023.28,3765.36 v2(1023.28,3784.5)
MCU_A14/B14/C14: C42.1 R43.2 U1.M1 | length 1473.2
  Top Signal w5: R43.2@561.21,5104.64 621.67,5104.64 630.98,5095.33 630.98,5088.65 640.38,5079.26 658.68,5079.26 808.33,4929.61 808.33,4086.29 821.1,4073.52 821.1,3968.59 U1.M1@950.75,3838.94
MCU_A15/B15/C15: C30.1 R45.2 U1.M2 | length 1645.3
  Top Signal w5: R45.2@561.21,2519.39 C30.1@625.3,2519.39 635.22,2519.39 719.15,2603.32 719.15,3611.3 715.2,3615.24 715.2,3775.15 v1(711.95,3778.4) ; v2(950.9,3820.69) U1.M2@969,3820.69
  Middle Signal w6: v1(711.95,3778.4) 908.61,3778.4 v2(950.9,3820.69)
MCU_B0/VDAC: C43.1 R46.2 U1.N2 | length 1496.5
  Top Signal w5: R46.2@559.89,5019.64 613.67,5019.64 613.67,5004.64 635.33,4982.99 698.47,4982.99 733.47,4947.99 791.72,4889.73 791.72,4083.73 809.18,4066.28 809.18,3886.3 910.98,3784.5 932.81,3784.5 U1.N2@950.9,3802.59
MCU_B1/DACC_OUT: C31.1 R48.2 U1.N3 | length 2150.5
  Top Signal w5: R48.2@571.87,1847 C31.1@625.3,1847 671.56,1893.27 685.16,1893.27 816.21,2024.32 816.21,3572.78 832.83,3589.4 832.83,3664.19 953.14,3784.5 U1.N3@969,3784.5
MCU_B3: C44.1 R49.2 U1.L4 | length 1840.3
  Top Signal w5: R49.2@561.21,2351.3 C44.1@625.3,2351.3 625.3,2371.83 643.93,2390.46 683.46,2390.46 746.12,2453.12 746.12,3624.11 750.19,3628.18 750.19,3657.28 734.06,3673.41 v1(734.06,3699.87) ; v2(1005.19,3802.59) U1.L4@1023.28,3802.59
  Middle Signal w5: v1(734.06,3699.87) 734.58,3700.39 734.58,3724.72 747.59,3737.73 918.28,3737.73 983.14,3802.59 v2(1005.19,3802.59)
MCU_B4: C32.1 R50.2 U1.M6 | length 1713.2
  Top Signal w4: v1(856.06,3621.98) 895.69,3621.98 1022.03,3748.31 U1.M6@1041.38,3748.31
  Top Signal w5: R50.2@561.21,4854.64 614.99,4854.64 657.36,4812.27 705.59,4812.27 776.06,4741.8 776.06,4078.64 797.26,4057.45 797.26,3880.07 776.06,3858.88 776.06,3779.25 808.44,3746.87 808.44,3628.65 801.77,3621.98 v1(801.77,3617.65)
  Middle Signal w6: v1(801.77,3617.65) 803.93,3619.81 853.89,3619.81 v1(856.06,3621.98)
MCU_B6: C45.1 R51.2 U1.J4 | length 2580.1
  Top Signal w5: R51.2@561.21,2015.1 C45.1@625.3,2015.1 634.82,2015.1 784.07,2164.34 784.07,3624.98 799.44,3640.35 799.44,3743.14 767.06,3775.52 767.06,4040.95 v1(778.25,4052.13) ; v2(1041.38,3838.79) U1.J4@1059.47,3838.79
  Bottom Signal w4: v1(778.25,4052.13) 851.37,4052.13 1041.38,3862.12 v2(1041.38,3838.79)
MCU_B7: C33.1 R52.2 U1.K4 | length 1095.5
  Top Signal w5: R52.2@561.21,4530.86 614.99,4530.86 614.99,4514.62 633.16,4496.45 694.89,4496.45 719.78,4471.56 719.78,4081.08 700.28,4061.58 v1(693.7,4061.58) ; v2(1023.28,3820.69) U1.K4@1041.38,3820.69
  Bottom Signal w4: v1(693.7,4061.58) 696.76,4064.64 737.26,4064.64 771.64,4030.26 861.93,4030.26 1023.28,3868.9 v2(1023.28,3820.69)
MCU_B8B9_N: C24.1 C34.1 R55.2 U1.N7 | length 785
  Top Signal w4: 1018.83,3672.18 1041.38,3694.73 U1.N7@1041.38,3712.12
  Top Signal w6: R55.2@481.25,3699.87 499.63,3718.25 512.66,3718.25 C34.1@534.9,3696.01 557.15,3718.26 567.52,3718.26 C24.1@590.34,3695.44 593.34,3698.44 593.34,3704.72 609.04,3720.42 614.42,3720.42 634.64,3700.2 634.64,3647.22 v1(634.73,3647.12) ; v1(856.28,3554.35) 875.48,3573.55 920.2,3573.55 1018.83,3672.18
  Middle Signal w6: v1(634.73,3647.12) 652.59,3647.12 734,3565.71 844.91,3565.71 v1(856.28,3554.35)
MCU_B8B9_P: C24.2 C46.1 R54.2 U1.M7 | length 788.9
  Top Signal w4: 1009.79,3680.11 1029.47,3699.8 1029.47,3717.05 1042.64,3730.21 U1.M7@1059.47,3730.21
  Top Signal w6: R54.2@481.25,3748.62 499.63,3730.25 512.64,3730.25 C46.1@534.9,3752.51 557.15,3730.26 562.17,3730.26 C24.2@590.34,3758.43 593.34,3755.43 593.34,3748.12 609.04,3732.42 619.39,3732.42 653.74,3698.07 653.74,3672.73 v1(660.48,3665.99) ; v1(856.06,3585.55) 915.23,3585.55 1009.79,3680.11
  Middle Signal w6: v1(660.48,3665.99) 663.54,3662.93 663.54,3653.14 738.97,3577.71 848.22,3577.71 v1(856.06,3585.55)
MCU_C0: C47.1 R56.2 U1.F1 | length 994.3
  Top Signal w5: R56.2@561.21,4691.04 614.99,4691.04 617,4689.03 v1(617,4662) ; v1(849.58,4196.12) 849.58,4135.55 1009.16,3975.97 1019.65,3975.97 1048.26,3947.36 U1.F1@1059.47,3947.36
  Middle Signal w5: v1(617,4662) 617,4428.69 v1(849.58,4196.12)
MCU_C1: C35.1 R57.2 U1.G1 | length 2348
  Top Signal w5: R57.2@561.21,2183.2 C35.1@625.3,2183.2 627.26,2185.17 631.2,2185.17 638.04,2192.01 638.04,2195.95 667.14,2225.04 689.53,2225.04 753.36,2288.87 v1(753.63,2288.87) ; v1(994.28,3963.42) 1019.47,3963.42 1040.22,3942.67 1040.22,3930.42 U1.G1@1041.38,3929.26
  Middle Signal w5: v1(753.63,2288.87) 753.63,3488.75 605.24,3637.14 605.24,3763.67 729.34,3887.77 729.34,3900.35 823.43,3994.44 915.3,3994.44 946.32,3963.42 v1(994.28,3963.42)
MCU_C4: C48.1 R60.2 U1.H6 | length 1317.4
  Top Signal w5: R60.2@561.21,4774.64 618.93,4774.64 646.22,4747.36 717.4,4747.36 722.19,4742.56 757.13,4707.62 v1(757.13,4076.48) ; v2(1095.67,3820.69) U1.H6@1113.76,3820.69
  Bottom Signal w4: v1(757.13,4076.48) 838.33,4076.48 1047.84,3866.98 1049.38,3866.98 v2(1095.67,3820.69)
MCU_C5: C36.1 R61.2 U1.G6 | length 2241.3
  Top Signal w5: R61.2@561.21,2267.25 C36.1@625.3,2267.25 668.07,2310.02 707.33,2310.02 759.19,2361.88 759.19,3757.25 746.54,3769.9 v1(746.54,3887.18) ; v2(1113.76,3838.79) U1.G6@1131.86,3838.79
  Middle Signal w5: v1(746.54,3887.18) 803.65,3944.3 1043.89,3944.3 1113.76,3874.42 v2(1113.76,3838.79)
MCU_C6: C49.1 R62.2 U1.G5 | length 2313.9
  Top Signal w5: R62.2@561.21,1931.05 C49.1@625.3,1931.05 631.23,1931.05 683.37,1983.19 800.63,2100.45 800.63,3578.22 820.81,3598.4 820.81,3764.5 v1(856.28,3799.97) ; v2(1095.67,3856.88) U1.G5@1113.76,3856.88
  Middle Signal w5: v1(856.28,3799.97) 856.28,3801.14 912.02,3856.88 v2(1095.67,3856.88)
MCU_C7: C37.1 R63.2 U1.G4 | length 960.2
  Top Signal w5: R63.2@561.36,4442.42 624.3,4442.42 656.2,4410.52 689.66,4410.52 700.46,4399.72 700.46,4090.6 v1(698.25,4088.4) ; v2(1077.57,3874.98) U1.G4@1095.67,3874.98
  Bottom Signal w4: v1(698.25,4088.4) 703.12,4088.4 709.53,4094.81 831.32,4094.81 1051.15,3874.98 v2(1077.57,3874.98)
MCU_C8C9_N: C25.1 C38.1 R65.2 U1.G2 | length 783.6
  Top Signal w4: v2(1041.38,3911.17) U1.G2@1059.47,3911.17
  Middle Signal w6: v1(677.17,3708.96) 652.59,3733.53 652.59,3765.12 792.68,3905.21 793.18,3905.71 1033.87,3905.71 1039.32,3911.17 v2(1041.38,3911.17)
  Bottom Signal w6: R65.2@481.25,3699.87 499.63,3718.25 512.66,3718.25 C38.1@534.9,3696.01 557.15,3718.26 571.64,3718.26 587.34,3702.56 587.34,3698.44 C25.1@590.34,3695.44 590.34,3696.42 614.85,3720.93 665.19,3720.93 v1(677.17,3708.96)
MCU_C8C9_P: C25.2 C50.1 R64.2 U1.G3 | length 750.2
  Top Signal w4: v2(1059.47,3893.07) U1.G3@1077.57,3893.07
  Middle Signal w6: v1(677.49,3739.85) 663.59,3753.74 663.59,3760.56 797.24,3894.21 797.74,3894.71 1057.84,3894.71 v2(1059.47,3893.07)
  Bottom Signal w6: R64.2@481.25,3748.62 499.63,3730.25 512.64,3730.25 C50.1@534.9,3752.51 557.15,3730.26 571.64,3730.26 587.34,3745.96 587.34,3755.43 C25.2@590.34,3758.43 590.34,3757.45 614.85,3732.93 670.58,3732.93 v1(677.49,3739.85)
MCU_RXD: R165.1 U9.6 | length 253.1
  Top Signal w5: U9.6@1177.55,5398.49 1177.55,5456.82 v1(1193.12,5472.39)
  Bottom Signal w5: R165.1@1131.89,5619.76 1131.89,5593.97 1193.12,5532.74 v1(1193.12,5472.39)
MCU_RXD_INT: J101.12 R165.2 U5.4 U27.13 | length 660.1
  Top Signal w4: v1(1435.7,5407.41) 1435.7,5476.73 J101.12@1438.46,5479.49
  Top Signal w5: U5.4@1108.58,5538.62 1126.45,5556.49 U27.13@1126.45,5606.07 1129.21,5608.83 1129.21,5629.49 1162.23,5662.52 v1(1175.17,5662.52)
  Middle Signal w5: v1(1175.17,5662.52) 1177.88,5662.52 1432.99,5407.41 v1(1435.7,5407.41) v1@1435.7,5398
  Bottom Signal w5: R165.2@1131.89,5682.75 1131.89,5681.77 1148.09,5665.57 1172.12,5665.57 v1(1175.17,5662.52)
MCU_TCK: R98.1 U1.M10 | length 3163.1
  Top Signal w4: 1023.92,3568.54 1113.76,3658.38 U1.M10@1113.76,3675.93
  Top Signal w5: v1(849.58,3339.17) 1023.92,3513.51 1023.92,3568.54
  Middle Signal w5: v1(676.18,3391) 483.11,3584.07 483.11,5015.3 543.97,5076.16 543.97,5076.73 551.64,5084.4 551.64,5550.84 569.68,5568.89 594.83,5594.04 653.72,5594.04 v1(695.1,5552.66)
  Bottom Signal w5: v1(676.18,3391) 728.01,3339.17 v1(849.58,3339.17) ; v1(695.1,5552.66) 709.65,5567.21 709.65,5601.47 R98.1@695.11,5616.01
MCU_TCK_INT: J101.4 R98.2 U4.1 U26.13 | length 1506.8
  Top Signal w4: v1(1638.46,5407.41) J101.4@1638.46,5479.49
  Top Signal w5: v1(683.53,5714.01) 683.53,5592.48 698.08,5577.94 704.36,5577.94 716.14,5566.16 716.14,5506.35 735.8,5486.69 753.55,5486.69 763.96,5497.09 U4.1@763.96,5505.16
  Middle Signal w5: v1(683.53,5714.01) 683.53,5714.08 707.29,5737.83 1308.03,5737.83 v1(1638.46,5407.41)
  Bottom Signal w5: v1(683.53,5714.01) 683.53,5690.57 R98.2@695.11,5679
